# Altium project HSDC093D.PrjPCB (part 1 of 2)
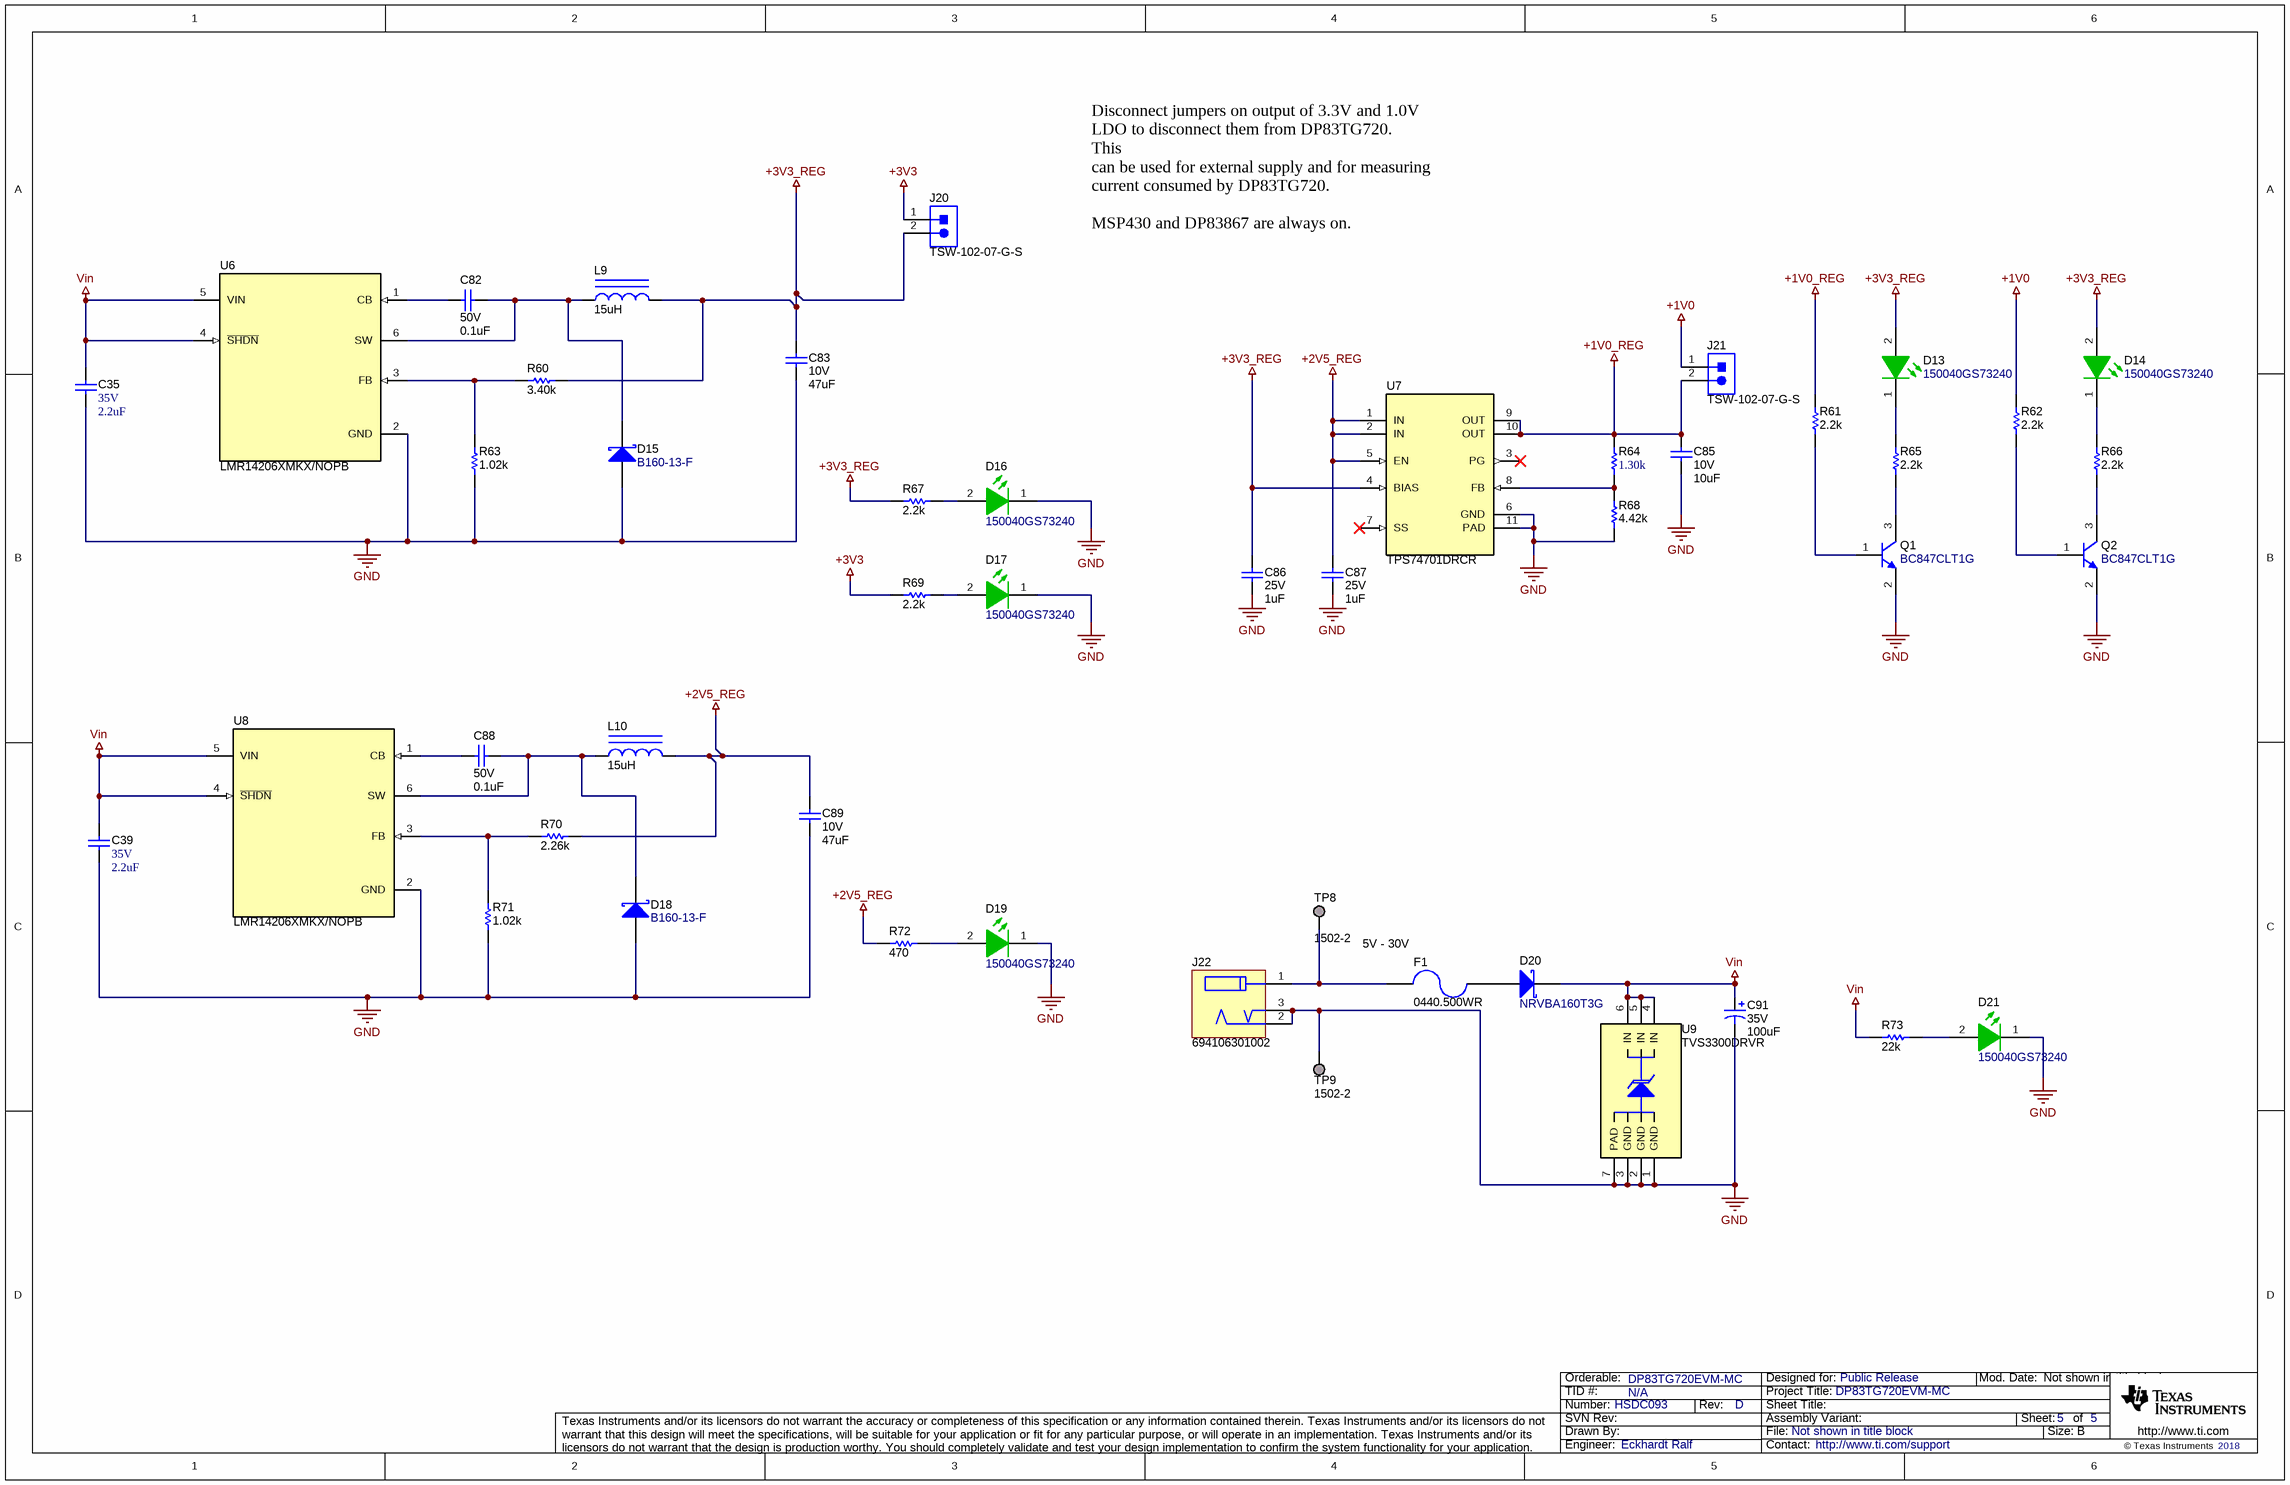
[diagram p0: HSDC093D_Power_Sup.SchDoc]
CopyrightYear: 2018; EVM_orderable: DP83TG720EVM-MC; PCB_Layout: Who did the Layout?; PCB_Rev: D; PRJ_Customer: Public Release; PRJ_Engineer: Eckhardt Ralf; PRJ_Number: HSDC093; PRJ_Title: DP83TG720EVM-MC; SCH_Rev: D; TechSupport: http://www.ti.com/support; TID: N/A
6 sheets, 280 parts. Net scope: global (net labels, ports and power ports of the same name join across sheets).
Board file: HSDC093D.PcbDoc
Sheets:
  HSDC093D_Power_Sup.SchDoc
  HSDC093D_Hardware.SchDoc
  HSDC093D_Cover_Sheet.SchDoc
  HSDC093D_Controller.SchDoc
  HSDC093D_867.SchDoc
  HSDC093D_720.SchDoc

## Sheet HSDC093D_Power_Sup.SchDoc
size 431 x 279 mm; Date: Not shown in title block; ApprovedBy: Not shown in title block; CheckedBy: Not shown in title block; Author: Not shown in title block; CompanyName: Not shown in title block; Engineer: Not shown in title block; Organization: Not shown in title block; Address1: Not shown in title block; Address2: Not shown in title block; Address3: Not shown in title block; Address4: Not shown in title block; DocumentNumber: 5; Revision: Use project parameter SCH_Rev; SheetNumber: 5; SheetTotal: 5; PageSetup: Record=PageOptions¦CenterHorizontal=True¦CenterVertical=True¦PrintScale=1.00¦XCorrection=1.00¦YCorrection=1.00¦PrintKind=0¦BorderSize=5000000¦LeftOffset=0¦BottomOffset=0¦Orientation=2¦PaperLength=1000¦PaperWidth=1000¦Scale=100¦PaperSource=15¦PrintQuality=600¦MediaType=1¦DitherType=10¦PaperKind=Letter¦PrintScaleMode=1

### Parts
C35  VDC_V: 35V  ValueDisplayed: 2.2uF  [0603]  (hidden comment: C1608X5R1V225K080AC)
C39  VDC_V: 35V  ValueDisplayed: 2.2uF  [0603]  (hidden comment: C1608X5R1V225K080AC)
C82  VDC_V: 50V  ValueDisplayed: 0.1uF  [0402]  (hidden comment: C1005X5R1H104K050BB)
C83  VDC_V: 10V  ValueDisplayed: 47uF  [0805_HV]  (hidden comment: C2012X5R1A476M125AC)
C85  VDC_V: 10V  ValueDisplayed: 10uF  [0402]  (hidden comment: GRM155R61A106ME11)
C86  VDC_V: 25V  ValueDisplayed: 1uF  [0402]  (hidden comment: GRM155R61E105KA12D)
C87  VDC_V: 25V  ValueDisplayed: 1uF  [0402]  (hidden comment: GRM155R61E105KA12D)
C88  VDC_V: 50V  ValueDisplayed: 0.1uF  [0402]  (hidden comment: C1005X5R1H104K050BB)
C89  VDC_V: 10V  ValueDisplayed: 47uF  [0805_HV]  (hidden comment: C2012X5R1A476M125AC)
C91  VDC_V: 35V  ValueDisplayed: 100uF  [CAPSMT_62_F80]  (hidden comment: EMVA350ADA101MF80G)
D13  150040GS73240  [WL-SMCC_0402_Green]
D14  150040GS73240  [WL-SMCC_0402_Green]
D15  B160-13-F  [SMA]
D16  150040GS73240  [WL-SMCC_0402_Green]
D17  150040GS73240  [WL-SMCC_0402_Green]
D18  B160-13-F  [SMA]
D19  150040GS73240  [WL-SMCC_0402_Green]
D20  NRVBA160T3G  [SMA]
D21  150040GS73240  [WL-SMCC_0402_Green]
F1  0440.500WR  [1206]
J20  TSW-102-07-G-S  [TSW-102-07-G-S]
J21  TSW-102-07-G-S  [TSW-102-07-G-S]
J22  694106301002  [Wurth_694106301002]
L9  ValueDisplayed: 15uH  [WE-TPC-LH]  (hidden comment: 744053150)
L10  ValueDisplayed: 15uH  [WE-TPC-LH]  (hidden comment: 744053150)
Q1  BC847CLT1G  [SOT-23]
Q2  BC847CLT1G  [SOT-23]
R60  ValueDisplayed: 3.40k  [0402]  (hidden comment: CRCW04023K40FKED)
R61  ValueDisplayed: 2.2k  [0402]  (hidden comment: CRCW04022K20JNED)
R62  ValueDisplayed: 2.2k  [0402]  (hidden comment: CRCW04022K20JNED)
R63  ValueDisplayed: 1.02k  [0402]  (hidden comment: CRCW04021K02FKED)
R64  ValueDisplayed: 1.30k  [0402]  (hidden comment: CRCW04021K30FKED)
R65  ValueDisplayed: 2.2k  [0402]  (hidden comment: CRCW04022K20JNED)
R66  ValueDisplayed: 2.2k  [0402]  (hidden comment: CRCW04022K20JNED)
R67  ValueDisplayed: 2.2k  [0402]  (hidden comment: CRCW04022K20JNED)
R68  ValueDisplayed: 4.42k  [0402]  (hidden comment: CRCW04024K42FKED)
R69  ValueDisplayed: 2.2k  [0402]  (hidden comment: CRCW04022K20JNED)
R70  ValueDisplayed: 2.26k  [0402]  (hidden comment: CRCW04022K26FKED)
R71  ValueDisplayed: 1.02k  [0402]  (hidden comment: CRCW04021K02FKED)
R72  ValueDisplayed: 470  [0402]  (hidden comment: RC0402FR-07470RL)
R73  ValueDisplayed: 22k  [0402]  (hidden comment: CRCW040222K0JNED)
TP8  1502-2  [Keystone1502-2]
TP9  1502-2  [Keystone1502-2]
U6  LMR14206XMKX/NOPB  [DDC0006A_N]
U7  TPS74701DRCR  [DRC0010J]
U8  LMR14206XMKX/NOPB  [DDC0006A_N]
U9  TVS3300DRVR  [DRV0006A]

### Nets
+1V0: J21.1 R62.2
+1V0_REG: C85.1 J21.2 R61.2 R64.1 U7.9(OUT) U7.10(OUT)
+2V5_REG: C87.1 C89.1 L10.2 R70.2 R72.1 U7.1(IN) U7.2(IN) U7.5(EN)
+3V3: J20.1 R69.1
+3V3_REG: C83.1 C86.1 D13.2(A) D14.2(A) J20.2 L9.2 R60.2 R67.1 U7.4(BIAS)
GND: C35.2 C39.2 C83.2 C85.2 C86.2 C87.2 C89.2 C91.2(-) D15.2(A) D16.1(K) D17.1(K) D18.2(A) D19.1(K) D21.1(K) J22.2 J22.3 Q1.2(E) Q2.2(E) R63.1 R68.1 R71.1 TP9.1 U6.2(GND) U7.6(GND) U7.11(PAD) U8.2(GND) U9.1(GND) U9.2(GND) U9.3(GND) U9.7(PAD)
Vin: C35.1 C39.1 C91.1(+) D20.1(K) R73.1 U6.4(~{SHDN}) U6.5(VIN) U8.4(~{SHDN}) U8.5(VIN) U9.4(IN) U9.5(IN) U9.6(IN)
NetC82_1: C82.1 U6.1(CB)
NetC82_2: C82.2 D15.1(K) L9.1 U6.6(SW)
NetC88_1: C88.1 U8.1(CB)
NetC88_2: C88.2 D18.1(K) L10.1 U8.6(SW)
NetD13_1: D13.1(K) R65.2
NetD14_1: D14.1(K) R66.2
NetD16_2: D16.2(A) R67.2
NetD17_2: D17.2(A) R69.2
NetD19_2: D19.2(A) R72.2
NetD20_2: D20.2(A) F1.1
NetD21_2: D21.2(A) R73.2
NetF1_2: F1.2 J22.1 TP8.1
NetQ1_1: Q1.1(B) R61.1
NetQ1_3: Q1.3(C) R65.1
NetQ2_1: Q2.1(B) R62.1
NetQ2_3: Q2.3(C) R66.1
NetR60_1: R60.1 R63.2 U6.3(FB)
NetR64_2: R64.2 R68.2 U7.8(FB)
NetR70_1: R70.1 R71.2 U8.3(FB)

Not connected (* = marked no-connect by the designer): U7 3(PG)* 7(SS)*

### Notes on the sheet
- Disconnect jumpers on output of 3.3V and 1.0V
  LDO to disconnect them from DP83TG720.
  This
  can be used for external supply and for measuring
  current consumed by DP83TG720.
  MSP430 and DP83867 are always on.
- 5V - 30V

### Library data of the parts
C35 C39 = CMP-0007020-5: CAP, CERM, 2.2 uF, 35 V, +/- 10%, X5R, 0603; Manufacturer: TDK; TaMin_C: -55°C; ESR_ohm: 7.674m; Polarized: N; SizeAreaWB_mm2: 4.68; Value1: 0.007674 ohm; U/M: EA; Value: 2.2uF; TaMax_C: 85°C; SizeZ_mm: 1; SizeX_mm: 1.6; SizeY_mm: 0.8; SizeArea_mm2: 1.28; Cap_F: 2.2µF; IRMS_A: 1.87823A; AEC Category: Q200
C82 C88 = CMP-0006279-2: CAP, CERM, 0.1 uF, 50 V, +/- 10%, X5R, 0402; Manufacturer: TDK; TaMin_C: -55°C; ESR_ohm: 0.039064; Polarized: N; SizeAreaWB_mm2: 3; Value1: 0.039064 ohm; U/M: EA; Value: 0.1uF; TaMax_C: 85°C; SizeZ_mm: 0.6; SizeX_mm: 1; SizeY_mm: 0.5; Cap_F: 100nF; IRMS_A: 814.669mA; AEC Category: Q200
C83 C89 = CMP-0007825-2: CAP, CERM, 47 uF, 10 V, +/- 20%, X5R, 0805; Manufacturer: TDK; TaMin_C: -55°C; ESR_ohm: 2.94m; Polarized: N; SizeAreaWB_mm2: 6.75; Value1: 0.00294 ohm; U/M: EA; Value: 47uF; TaMax_C: 85°C; SizeZ_mm: 1.45; SizeX_mm: 2; SizeY_mm: 1.25; Cap_Case: 0805; SizeArea_mm2: 2.5; Cap_F: 47µF; IRMS_A: 3.80451A; AEC Category: Q200
C85 = CMP-0006564-2: CAP, CERM, 10 uF, 10 V, +/- 20%, X5R, 0402; Manufacturer: MuRata; TaMin_C: -55°C; Polarized: N; SizeAreaWB_mm2: 3; Value1: Unknown; U/M: EA; Value: 10uF; TaMax_C: 85°C; SizeZ_mm: 0.6; SizeX_mm: 1; SizeY_mm: 0.5; Cap_F: 10µF; AEC Category: Q200
C86 C87 = CMP-0006608-2: CAP, CERM, 1 uF, 25 V, +/- 10%, X5R, 0402; Manufacturer: MuRata; TaMin_C: -55°C; Polarized: N; SizeAreaWB_mm2: 3; Value1: Unknown; U/M: EA; Value: 1uF; TaMax_C: 85°C; SizeZ_mm: 0.6; SizeX_mm: 1; SizeY_mm: 0.5; Cap_F: 1µF; AEC Category: Q200
C91 = CMP-0010800-1: CAP, AL, 100 uF, 35 V, +/- 20%, SMD; Manufacturer: Chemi-Con; TaMin_C: -40°C; Polarized: Y; SizeAreaWB_mm2: 73.96; Value1: Unknown; U/M: EA; Value: 100uF; TaMax_C: 85°C; SizeZ_mm: 7.7; SizeX_mm: 6.6; Cap_Case: F80; SizeArea_mm2: 43.56; CompType: Capacitor; Cap_F: 100µF; IRMS_A: 120mA; AEC Category: Q200
D13 D14 D16 D17 D19 D21 = CMP-0081765-2: LED, Green, SMD; Manufacturer: Wurth Elektronik; Vr_V: 5V; Io_A: 20mA; Tjmax_C: 95°C; Ir_A: 10µA; Power_TotalModule: 99mW; Value2: 3.2V; SizeArea_mm2: 0.5; SizeX_mm: 1; Value1: 0.099W; Angle: 120; Type: InGaN; SizeAreaWB_mm2: 3
D15 D18 = CMP-0028389-2: Diode, Schottky, 60 V, 1 A, SMA; Manufacturer: Diodes Inc.; Green_Lifecycle: Not Set; SizeAreaWB_mm2: 37.3428; Green_REACh: Incomplete; TJmax_C: 150°C; AEC Category: Q101; SizeZ_mm: 2.87; RJC_CperW: 20; Io_A: 1A; SizeArea_mm2: 16.3228; Vf_V: 700mV; Value2: 0.7V; SizeY_mm: 2.92; Vr_V: 60V; SizeX_mm: 5.59; Value: 60V
D20 = CMP-0028762-2: Diode, Schottky, 60 V, 1 A, AEC-Q101, SMA; Manufacturer: ON Semiconductor; SizeY_mm: 2.92; Value2: 0.51V; Green_Lifecycle: Active; Vf_V: 510mV; SizeAreaWB_mm2: 37.3428; SizeX_mm: 5.59; SizeZ_mm: 2.87; Green_REACh: Passed; AEC Qualified: Y; Vr_V: 60V; TJmax_C: 150°C; AEC Category: Q101; Value1: 1A; Value: 60V; SizeArea_mm2: 16.3228
F1 = CMP-0003452-2: Fuse, 0.5 A, 63VAC/VDC, SMD; Manufacturer: Littelfuse; Irating_A: 500mA; SizeAreaWB_mm2: 10.92; Interrupt_AC: 50A; VAC_V: 63V; SizeZ_mm: 1.35; SizeX_mm: 3.2; SizeY_mm: 1.6; SizeArea_mm2: 5.12; Rtyp_Ohm: 0.814; MeltingTyp: 0.02642
J20 J21 = CMP-0075405-3: Header, 100mil, 2x1, Gold, TH; Manufacturer: Samtec; Pitch_mm: 2.54; Cert_VDE: N; Gender: Male; Cert_CSA: Y; Voltage_V: 550V; Green_REACh: Passed; Current_A: 6.3A; Green_Lifecycle: Active; Row_Count: 1
J22 = CMP-0054778-4: WR-DC DC Power Jack, R/A, TH; Manufacturer: Wurth Elektronik; Gender: Male
L9 L10 = CMP-0064420-2: Inductor, Shielded Drum Core, Ferrite, 15 uH, 1.15 A, 0.07 ohm, SMD; Manufacturer: Wurth Elektronik; Isat: 1.15A @ 35% inductance drop; Irms: 1.38A @ 30C rise; Green_Lifecycle: Active; SizeAreaWB_mm2: 60.84; DCR_ohm: 0.07; Green_REACh: Passed; Value: 15uH; Imax_A: 1.15A; SizeZ_mm: 2.8; SizeX_mm: 5.8; SizeArea_mm2: 33.64; Ind_H: 15µH; AEC Category: Q200
Q1 Q2 = CMP-0000376-2: Transistor, NPN, 45 V, 0.1 A, SOT-23; Manufacturer: ON Semiconductor; TaMax_C: 150°C; Value2: 800; Value1: 0.1 A; Vcesat1_V: 700mV; SizeX_mm: 2.5; SizeY_mm: 3; TaMin_C: -55°C; IcRated_A: 100mA; CompType: BJT; SizeZ_mm: 1.1; Value: 45 V; SizeArea_mm2: 7.5; NPN: 1; Vceo_V: 45V; PNP: 0; AEC Category: Q101; SizeAreaWB_mm2: 14; U/M: EA
R60 = CMP-0026334-2: RES, 3.40 k, 1%, 0.063 W, AEC-Q200 Grade 0, 0402; Manufacturer: Vishay-Dale; Power_W: 63mW; TempCo: 100 ppm/C; Value_Code: 3k40; Value: 3.40k; EIA_Code: E96; Res_ohm: 3.4k; SizeX_mm: 1; SizeY_mm: 0.5; SizeZ_mm: 0.6; Value2: 0.063W; AEC Qualified: Y; VDC_V: 50V; AEC Category: Q200; AEC Grade: 0
R61 R62 R65-R67 R69 = CMP-0026890-5: RES, 2.2 k, 5%, 0.063 W, AEC-Q200 Grade 0, 0402; Manufacturer: Vishay-Dale; Power_W: 63mW; TempCo: 200 ppm/C; Value_Code: 2k20; Value: 2.2k; EIA_Code: E24; SizeX_mm: 1; SizeY_mm: 0.5; SizeZ_mm: 0.6; Value2: 0.063W; AEC Qualified: Y; VDC_V: 50V; AEC Category: Q200; AEC Grade: 0
R63 R71 = CMP-0026072-3: RES, 1.02 k, 1%, 0.063 W, AEC-Q200 Grade 0, 0402; Manufacturer: Vishay-Dale; Power_W: 63mW; TempCo: 100 ppm/C; Value_Code: 1k02; Value: 1.02k; EIA_Code: E96; SizeX_mm: 1; SizeY_mm: 0.5; SizeZ_mm: 0.6; Value2: 0.063W; AEC Qualified: Y; VDC_V: 50V; AEC Category: Q200; AEC Grade: 0
R64 = CMP-0026082-3: RES, 1.30 k, 1%, 0.063 W, AEC-Q200 Grade 0, 0402; Manufacturer: Vishay-Dale; Power_W: 63mW; TempCo: 100 ppm/C; Value_Code: 1k30; Value: 1.30k; EIA_Code: E96; Res_ohm: 1.3k; SizeX_mm: 1; SizeY_mm: 0.5; SizeZ_mm: 0.6; Value2: 0.063W; AEC Qualified: Y; VDC_V: 50V; AEC Category: Q200; AEC Grade: 0
R68 = CMP-0026409-2: RES, 4.42 k, 1%, 0.063 W, AEC-Q200 Grade 0, 0402; Manufacturer: Vishay-Dale; Power_W: 63mW; TempCo: 100 ppm/C; Value_Code: 4k42; Value: 4.42k; EIA_Code: E96; SizeX_mm: 1; SizeY_mm: 0.5; SizeZ_mm: 0.6; Value2: 0.063W; AEC Qualified: Y; VDC_V: 50V; AEC Category: Q200; AEC Grade: 0
R70 = CMP-0026233-2: RES, 2.26 k, 1%, 0.063 W, AEC-Q200 Grade 0, 0402; Manufacturer: Vishay-Dale; Power_W: 63mW; TempCo: 100 ppm/C; Value_Code: 2k26; Value: 2.26k; EIA_Code: E96; SizeX_mm: 1; SizeY_mm: 0.5; SizeZ_mm: 0.6; Value2: 0.063W; AEC Qualified: Y; VDC_V: 50V; AEC Category: Q200; AEC Grade: 0
R72 = CMP-0026736-1: RES, 470, 1%, 0.063 W, 0402; Manufacturer: Yageo America; Power_W: 63mW; TempCo: 100 ppm/C; Value_Code: 470R; U/M: EA; Value: 470; SizeX_mm: 1; SizeY_mm: 0.5; SizeZ_mm: 0.6; Value2: 0.063W; AEC Qualified: N; VDC_V: 50V; AEC Category: Q200
R73 = CMP-0026879-3: RES, 22 k, 5%, 0.063 W, AEC-Q200 Grade 0, 0402; Manufacturer: Vishay-Dale; Power_W: 63mW; TempCo: 200 ppm/C; Value_Code: 22k0; Value: 22k; EIA_Code: E24; SizeX_mm: 1; SizeY_mm: 0.5; SizeZ_mm: 0.6; Value2: 0.063W; AEC Qualified: Y; VDC_V: 50V; AEC Category: Q200; AEC Grade: 0
TP8 TP9 = CMP-0055113-1: Terminal, Turret, TH, Double; Manufacturer: Keystone; CT: FALSE; Green_REACh: Passed; CompType: Turret Terminal; Green_Lifecycle: Active
U6 U8 = CMP-0076377-2: SIMPLE SWITCHER(R) 4.5V to 42V, 0.6A Step-Down DC/DC Switching Regulator in SOT-23 Package, DDC0006A (SOT-23-T-6); Alternate PartNumber: LMR14206XMKE/NOPB; Manufacturer: Texas Instruments; SizeZ_mm: 0.87; SizeX_mm: 1.65; SizeY_mm: 2.95; SizeArea_mm2: 4.8675; CompType: IC; U/M: EA; SizeAreaWB_mm2: 10.4675
U7 = CMP-0036362-5: Single Output LDO, 500mA, Adj. (0.8 to 3.6V), Programmable Soft-Start, DRC0010J (VSON-10); Manufacturer: Texas Instruments; Vout Adj(Min)(V): 0.8; Rating: Catalog; Iq(Typ)(mA): 1; CompType: IC; Accuracy(%): 2; SizeX_mm: 3; Vdo(Typ)(mV): 50; Vin(Max)(V): 5.5; AEC Category: Q200; Vout Adj(Max)(V): 3.6; Power Good: TRUE; AEC Qualified: N; SizeAreaWB_mm2: 16; SizeArea_mm2: 9; Iout(Max)(A): 0.5
U9 = CMP-0013424-7: 33-V Precision Surge Protection Clamp, DRV0006A (WSON-6); Manufacturer: Texas Instruments; Alternate PartNumber: TVS3300DRVT; SizeX_mm: 2; CompType: IC; SizeZ_mm: 0.8; SizeArea_mm2: 4; SizeAreaWB_mm2: 9; U/M: EA

## Sheet HSDC093D_Hardware.SchDoc
size 431 x 279 mm; Date: Not shown in title block; ApprovedBy: Not shown in title block; CheckedBy: Not shown in title block; Author: Not shown in title block; CompanyName: Not shown in title block; Engineer: Not shown in title block; Organization: Not shown in title block; Address1: Not shown in title block; Address2: Not shown in title block; Address3: Not shown in title block; Address4: Not shown in title block; DocumentNumber: 1; Revision: Use project parameter SCH_Rev; SheetNumber: 1; SheetTotal: 5; PageSetup: Record=PageOptions¦CenterHorizontal=True¦CenterVertical=True¦PrintScale=1.00¦XCorrection=1.00¦YCorrection=1.00¦PrintKind=0¦BorderSize=5000000¦LeftOffset=0¦BottomOffset=0¦Orientation=2¦PaperLength=1000¦PaperWidth=1000¦Scale=100¦PaperSource=15¦PrintQuality=600¦MediaType=1¦DitherType=10¦PaperKind=Letter¦PrintScaleMode=1
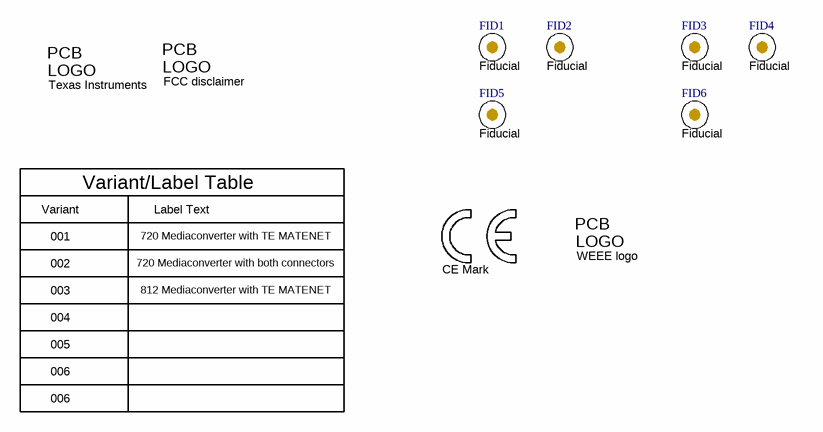
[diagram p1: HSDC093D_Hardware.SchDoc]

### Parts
FID1  Fiducial  [Fiducial10-30]
FID2  Fiducial  [Fiducial10-30]
FID3  Fiducial  [Fiducial10-30]
FID4  Fiducial  [Fiducial10-30]
FID5  Fiducial  [Fiducial10-30]
FID6  Fiducial  [Fiducial10-30]
Logo1  CE Mark  [CE_Mark_5mm]  (no BOM)
Logo2  FCC disclaimer  [FCC_disclaimer]  (no BOM)
Logo3  Texas Instruments  [TI_Stacked_Overlay_Small]  (no BOM)
Logo4  WEEE logo  [WEEE_Minimum]  (no BOM)

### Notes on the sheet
- Variant/Label Table
- Variant
- 001
- Label Text
- 720 Mediaconverter with TE MATENET
- 002
- 003
- 004
- 720 Mediaconverter with both connectors
- 812 Mediaconverter with TE MATENET
- 005
- 006

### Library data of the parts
FID1-FID6 = CMP-0077181-1: Fiducial mark.  There is nothing to buy or mount.
Logo1 = CMP-0074844-1: SymbolCreator: a0412235
Logo2 = CMP-0074847-1: FCC_disclaimer; Library Reference: Logo
Logo3 = CMP-0074838-1: Texas Instrument Corporate Signature; Library Reference: Logo; SymbolCreator: a0412235; Lib Reference: TI_Logo
Logo4 = CMP-0074769-1

## Sheet HSDC093D_Cover_Sheet.SchDoc
size 431 x 279 mm; Date: Not shown in title block; ApprovedBy: Not shown in title block; CheckedBy: Not shown in title block; Author: Not shown in title block; CompanyName: Not shown in title block; Engineer: Not shown in title block; Organization: Not shown in title block; Address1: Not shown in title block; Address2: Not shown in title block; Address3: Not shown in title block; Address4: Not shown in title block; DocumentNumber: 1; Revision: Use project parameter SCH_Rev; SheetNumber: 1; SheetTotal: 5; PageSetup: Record=PageOptions¦CenterHorizontal=True¦CenterVertical=True¦PrintScale=1.00¦XCorrection=1.00¦YCorrection=1.00¦PrintKind=0¦BorderSize=5000000¦LeftOffset=0¦BottomOffset=0¦Orientation=2¦PaperLength=1000¦PaperWidth=1000¦Scale=100¦PaperSource=15¦PrintQuality=600¦MediaType=1¦DitherType=10¦PaperKind=Letter¦PrintScaleMode=1

## Sheet HSDC093D_Controller.SchDoc
size 431 x 279 mm; Date: Not shown in title block; ApprovedBy: Not shown in title block; CheckedBy: Not shown in title block; Author: Not shown in title block; CompanyName: Not shown in title block; Engineer: Not shown in title block; Organization: Not shown in title block; Address1: Not shown in title block; Address2: Not shown in title block; Address3: Not shown in title block; Address4: Not shown in title block; DocumentNumber: 4; Revision: Use project parameter SCH_Rev; SheetNumber: 4; SheetTotal: 5; PageSetup: Record=PageOptions¦CenterHorizontal=True¦CenterVertical=True¦PrintScale=1.00¦XCorrection=1.00¦YCorrection=1.00¦PrintKind=0¦BorderSize=5000000¦LeftOffset=0¦BottomOffset=0¦Orientation=2¦PaperLength=1000¦PaperWidth=1000¦Scale=100¦PaperSource=15¦PrintQuality=600¦MediaType=1¦DitherType=10¦PaperKind=Letter¦PrintScaleMode=1
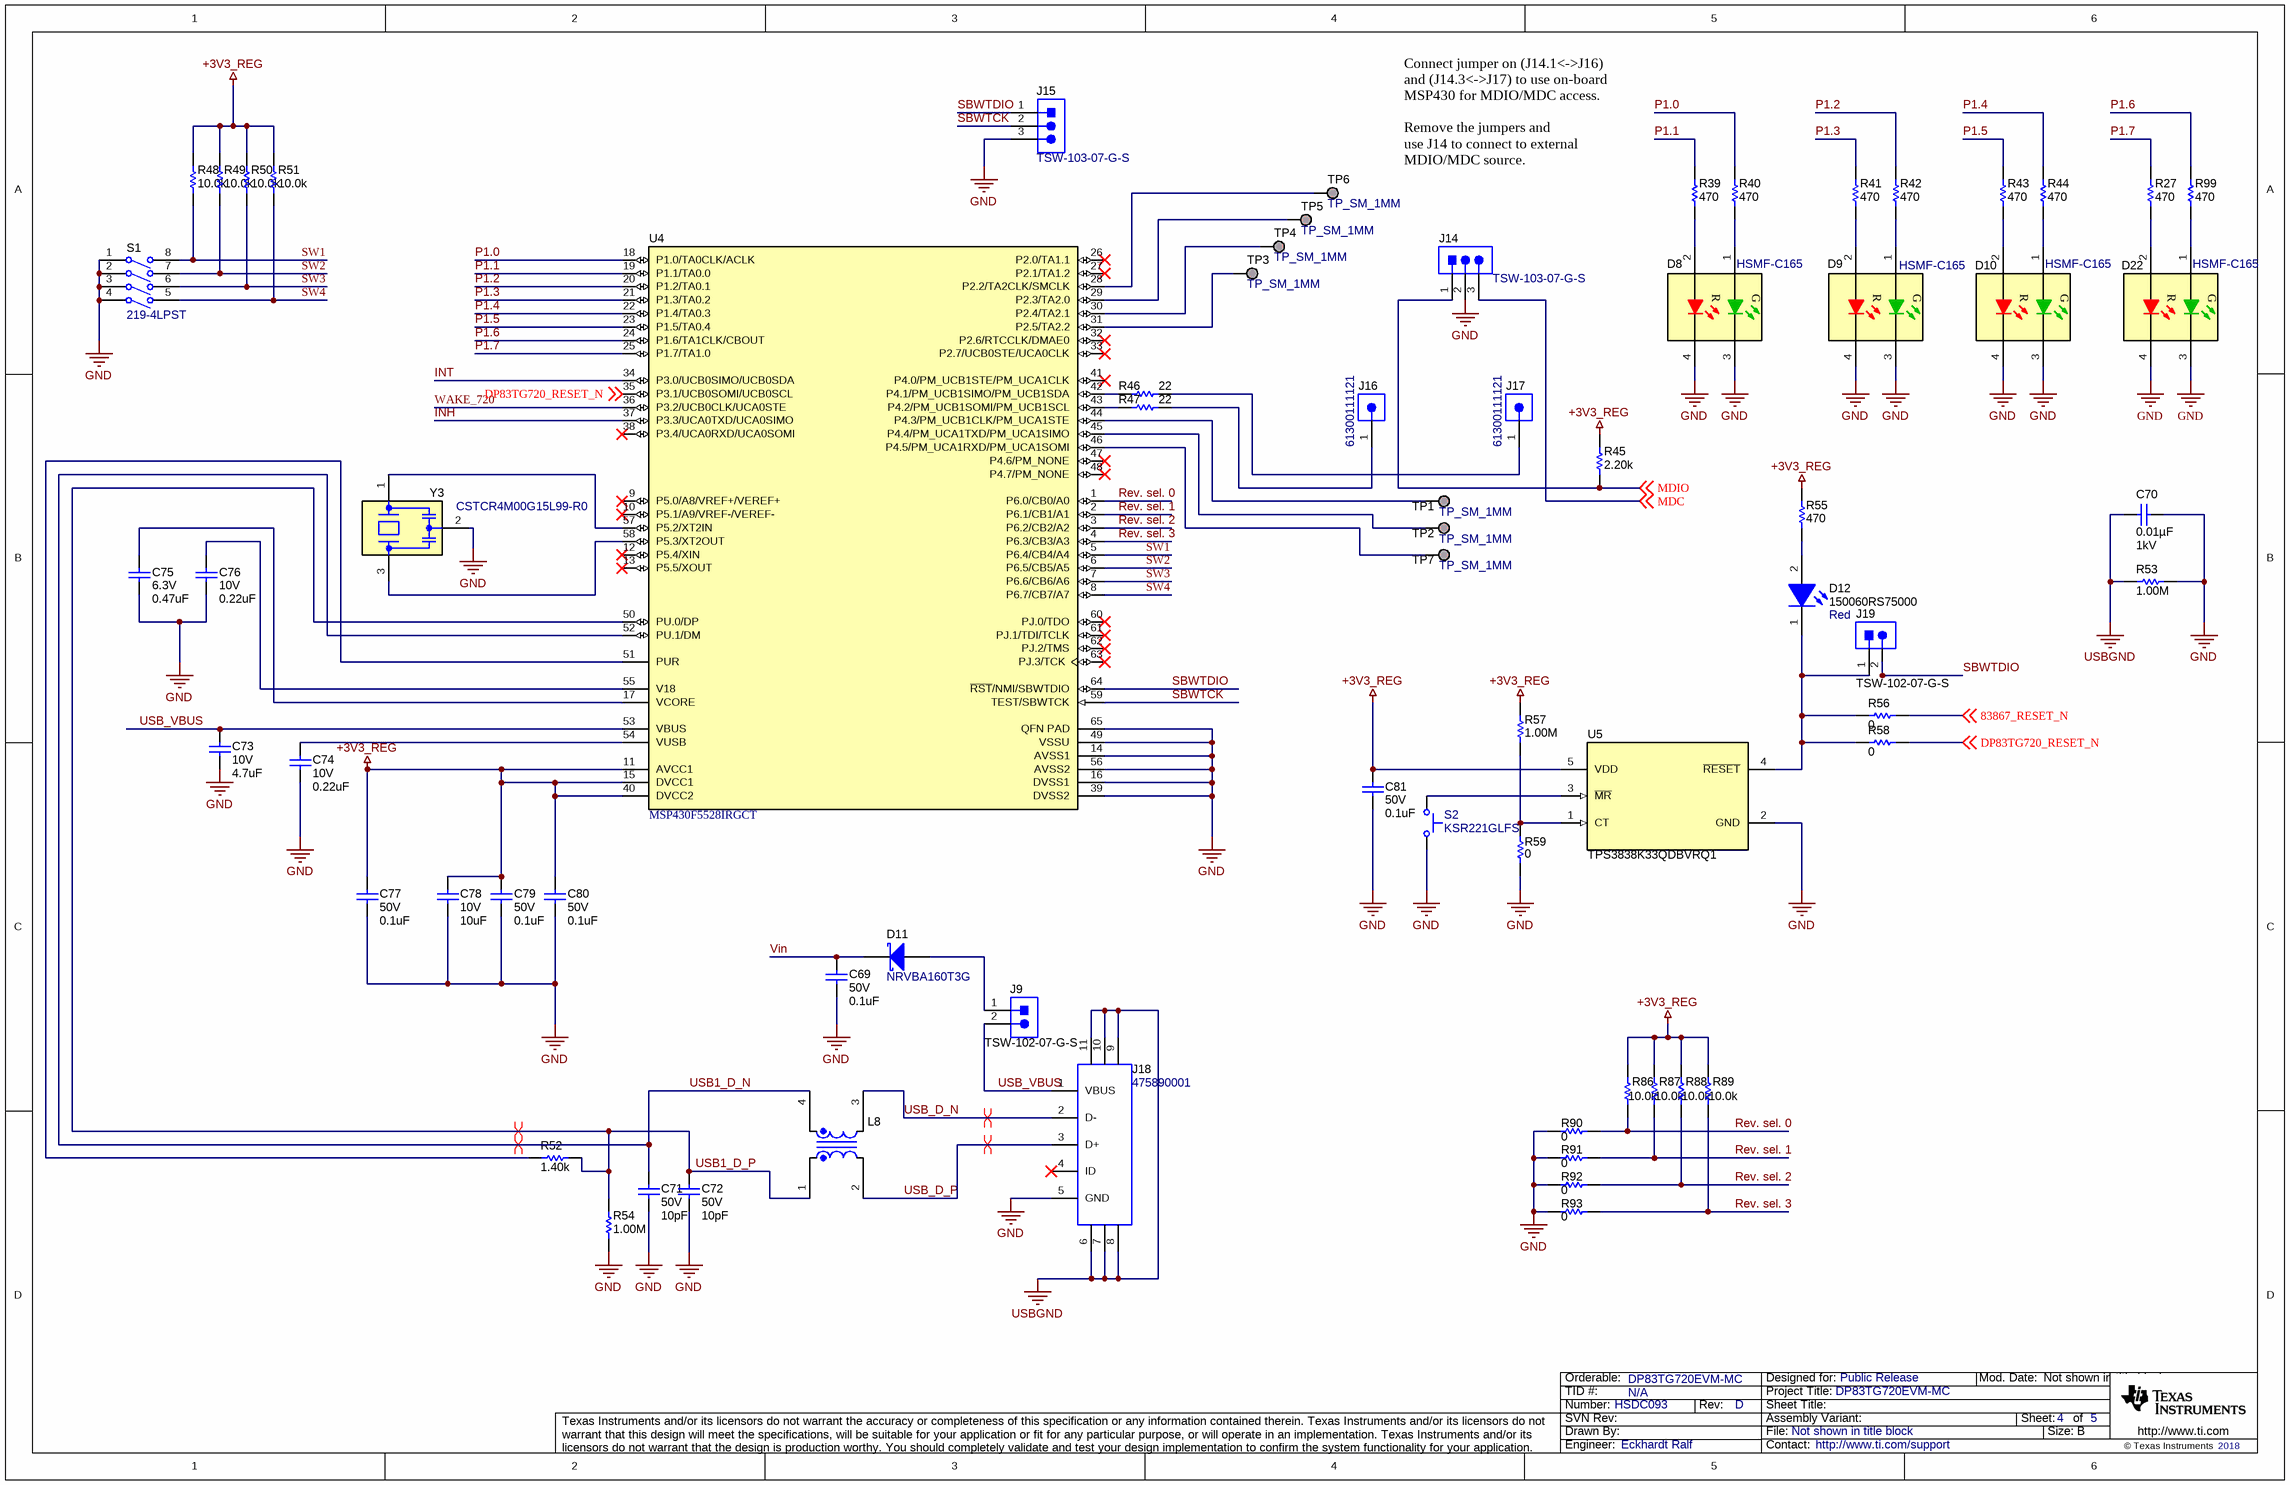
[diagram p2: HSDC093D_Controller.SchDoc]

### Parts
C69  VDC_V: 50V  ValueDisplayed: 0.1uF  [0402]  (hidden comment: C1005X5R1H104K050BB)
C70  ValueDisplayed: 0.01µF  VDC_V: 1kV  [1206]  (hidden comment: C1206X103KDRAC7800)
C71  VDC_V: 50V  ValueDisplayed: 10pF  [0402]  (hidden comment: GRM1555C1H100FA01D)
C72  VDC_V: 50V  ValueDisplayed: 10pF  [0402]  (hidden comment: GRM1555C1H100FA01D)
C73  VDC_V: 10V  ValueDisplayed: 4.7uF  [0402_065]  (hidden comment: C1005X5R1A475K050BC)
C74  VDC_V: 10V  ValueDisplayed: 0.22uF  [0402]  (hidden comment: GRM155R61A224KE19D)
C75  VDC_V: 6.3V  ValueDisplayed: 0.47uF  [0402]  (hidden comment: 04026D474KAT2A)
C76  VDC_V: 10V  ValueDisplayed: 0.22uF  [0402]  (hidden comment: GRM155R61A224KE19D)
C77  VDC_V: 50V  ValueDisplayed: 0.1uF  [0402]  (hidden comment: C1005X5R1H104K050BB)
C78  VDC_V: 10V  ValueDisplayed: 10uF  [0402]  (hidden comment: GRM155R61A106ME11)
C79  VDC_V: 50V  ValueDisplayed: 0.1uF  [0402]  (hidden comment: C1005X5R1H104K050BB)
C80  VDC_V: 50V  ValueDisplayed: 0.1uF  [0402]  (hidden comment: C1005X5R1H104K050BB)
C81  VDC_V: 50V  ValueDisplayed: 0.1uF  [0402]  (hidden comment: C1005X5R1H104K050BB)
D8  HSMF-C165  [HSMF-C165_RG]
D9  HSMF-C165  [HSMF-C165_RG]
D10  HSMF-C165  [HSMF-C165_RG]
D11  NRVBA160T3G  [SMA]
D12  150060RS75000  value Red  [WL-SMCW_RED]
D22  HSMF-C165  [HSMF-C165_RG]
J9  TSW-102-07-G-S  [TSW-102-07-G-S]
J14  TSW-103-07-G-S  [TSW-103-07-G-S]
J15  TSW-103-07-G-S  [TSW-103-07-G-S]
J16  61300111121  [WURTH_61300111121]
J17  61300111121  [WURTH_61300111121]
J18  475890001  [Molex_0475890001]
J19  TSW-102-07-G-S  [TSW-102-07-G-S]
L8  744232090  [WE-CNSW_1206]  (value not drawn)
R27  ValueDisplayed: 470  [0402]  (hidden comment: RC0402FR-07470RL)
R39  ValueDisplayed: 470  [0402]  (hidden comment: RC0402FR-07470RL)
R40  ValueDisplayed: 470  [0402]  (hidden comment: RC0402FR-07470RL)
R41  ValueDisplayed: 470  [0402]  (hidden comment: RC0402FR-07470RL)
R42  ValueDisplayed: 470  [0402]  (hidden comment: RC0402FR-07470RL)
R43  ValueDisplayed: 470  [0402]  (hidden comment: RC0402FR-07470RL)
R44  ValueDisplayed: 470  [0402]  (hidden comment: RC0402FR-07470RL)
R45  ValueDisplayed: 2.20k  [0402]  (hidden comment: ERJ-2RKF2201X)
R46  ValueDisplayed: 22  [0402]  (hidden comment: ERJ-2GEJ220X)
R47  ValueDisplayed: 22  [0402]  (hidden comment: ERJ-2GEJ220X)
R48  ValueDisplayed: 10.0k  [0402]  (hidden comment: RT0402BRD0710KL)
R49  ValueDisplayed: 10.0k  [0402]  (hidden comment: RT0402BRD0710KL)
R50  ValueDisplayed: 10.0k  [0402]  (hidden comment: RT0402BRD0710KL)
R51  ValueDisplayed: 10.0k  [0402]  (hidden comment: RT0402BRD0710KL)
R52  ValueDisplayed: 1.40k  [0402]  (hidden comment: CRCW04021K40FKED)
R53  ValueDisplayed: 1.00M  [0603]  (hidden comment: RMCF0603FG1M00)
R54  ValueDisplayed: 1.00M  [0402]  (hidden comment: ERJ-2RKF1004X)
R55  ValueDisplayed: 470  [0402]  (hidden comment: RC0402FR-07470RL)
R56  ValueDisplayed: 0  [0402]  (hidden comment: CRCW04020000Z0EDHP)
R57  ValueDisplayed: 1.00M  [0402]  (hidden comment: ERJ-2RKF1004X)
R58  ValueDisplayed: 0  [0402]  (hidden comment: CRCW04020000Z0EDHP)
R59  ValueDisplayed: 0  [0402]  (hidden comment: CRCW04020000Z0EDHP)
R86  ValueDisplayed: 10.0k  [0402]  (hidden comment: RT0402BRD0710KL)
R87  ValueDisplayed: 10.0k  [0402]  (hidden comment: RT0402BRD0710KL)
R88  ValueDisplayed: 10.0k  [0402]  (hidden comment: RT0402BRD0710KL)
R89  ValueDisplayed: 10.0k  [0402]  (hidden comment: RT0402BRD0710KL)
R90  ValueDisplayed: 0  [0402]  (hidden comment: CRCW04020000Z0EDHP)
R91  ValueDisplayed: 0  [0402]  (hidden comment: CRCW04020000Z0EDHP)
R92  ValueDisplayed: 0  [0402]  (hidden comment: CRCW04020000Z0EDHP)
R93  ValueDisplayed: 0  [0402]  (hidden comment: CRCW04020000Z0EDHP)
R99  ValueDisplayed: 470  [0402]  (hidden comment: RC0402FR-07470RL)
S1  219-4LPST  [SW_219-4LPST]
S2  KSR221GLFS  [KSR]
TP1  TP_SM_1MM  [TP_SM_1MM]  (no BOM)
TP2  TP_SM_1MM  [TP_SM_1MM]  (no BOM)
TP3  TP_SM_1MM  [TP_SM_1MM]  (no BOM)
TP4  TP_SM_1MM  [TP_SM_1MM]  (no BOM)
TP5  TP_SM_1MM  [TP_SM_1MM]  (no BOM)
TP6  TP_SM_1MM  [TP_SM_1MM]  (no BOM)
TP7  TP_SM_1MM  [TP_SM_1MM]  (no BOM)
U4  MSP430F5528IRGCT  [RGC0064B]
U5  TPS3838K33QDBVRQ1  [DBV0005A_N]
Y3  CSTCR4M00G15L99-R0  [Murata_CSTCR_G15L]

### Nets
+3V3_REG: C77.1 C78.1 C79.1 C80.1 C81.1 R45.2 R48.2 R49.2 R50.2 R51.2 R55.2 R57.1 R86.2 R87.2 R88.2 R89.2 U4.11(AVCC1) U4.15(DVCC1) U4.40(DVCC2) U5.5(VDD)
GND: C69.2 C70.1 C71.1 C72.1 C73.2 C74.1 C75.1 C76.2 C77.2 C78.2 C79.2 C80.2 C81.2 D8.3(K) D8.4(K) D9.3(K) D9.4(K) D10.3(K) D10.4(K) D22.3(K) D22.4(K) J14.2 J15.3 J18.5(GND) R53.2 R54.2 R59.1 R90.2 R91.2 R92.2 R93.2 S1.1(A1) S1.2(A2) S1.3(A3) S1.4(A4) S2.2 U4.14(AVSS1) U4.16(DVSS1) U4.39(DVSS2) U4.49(VSSU) U4.56(AVSS2) U4.65(QFN_PAD) U5.2(GND) Y3.2(GND)
USBGND: C70.2 J18.6 J18.7 J18.8 J18.9 J18.10 J18.11 R53.1
Vin: C69.1 D11.1(K)
83867_RESET_N: R56.2 ; off-sheet 83867_RESET_N
DP83TG720_RESET_N: R58.2 U4.35(P3.1/UCB0SOMI/UCB0SCL) ; off-sheet DP83TG720_RESET_N
INH: U4.37(P3.3/UCA0TXD/UCA0SIMO)
INT: U4.34(P3.0/UCB0SIMO/UCB0SDA)
MDC: J14.3 ; off-sheet MDC
MDIO: J14.1 R45.1 ; off-sheet MDIO
P1.0: R40.2 U4.18(P1.0/TA0CLK/ACLK)
P1.1: R39.2 U4.19(P1.1/TA0.0)
P1.2: R42.2 U4.20(P1.2/TA0.1)
P1.3: R41.2 U4.21(P1.3/TA0.2)
P1.4: R44.2 U4.22(P1.4/TA0.3)
P1.5: R43.2 U4.23(P1.5/TA0.4)
P1.6: R99.2 U4.24(P1.6/TA1CLK/CBOUT)
P1.7: R27.2 U4.25(P1.7/TA1.0)
Rev. sel. 0: R86.1 R90.1 U4.1(P6.0/CB0/A0)
Rev. sel. 1: R87.1 R91.1 U4.2(P6.1/CB1/A1)
Rev. sel. 2: R88.1 R92.1 U4.3(P6.2/CB2/A2)
Rev. sel. 3: R89.1 R93.1 U4.4(P6.3/CB3/A3)
SBWTCK: J15.2 U4.59(TEST/SBWTCK)
SBWTDIO: J15.1 J19.2 U4.64(~{RST}/NMI/SBWTDIO)
SW1: R48.1 S1.8(B1) U4.5(P6.4/CB4/A4)
SW2: R49.1 S1.7(B2) U4.6(P6.5/CB5/A5)
SW3: R50.1 S1.6(B3) U4.7(P6.6/CB6/A6)
SW4: R51.1 S1.5(B4) U4.8(P6.7/CB7/A7)
USB1_D_N: C71.2 L8.4 U4.52(PU.1/DM)
USB1_D_P: C72.2 L8.1 R52.2 R54.1 U4.50(PU.0/DP)
USB_D_N: J18.2(D-) L8.3
USB_D_P: J18.3(D+) L8.2
USB_VBUS: C73.1 J9.2 J18.1(VBUS) U4.53(VBUS)
WAKE_720: U4.36(P3.2/UCB0CLK/UCA0STE)
NetC74_2: C74.2 U4.54(VUSB)
NetC75_2: C75.2 U4.17(VCORE)
NetC76_1: C76.1 U4.55(V18)
NetD8_1: D8.1(A) R40.1
NetD8_2: D8.2(A) R39.1
NetD9_1: D9.1(A) R42.1
NetD9_2: D9.2(A) R41.1
NetD10_1: D10.1(A) R44.1
NetD10_2: D10.2(A) R43.1
NetD11_2: D11.2(A) J9.1
NetD12_1: D12.1(K) J19.1 R56.1 R58.1 U5.4(~{RESET})
NetD12_2: D12.2(A) R55.1
NetD22_1: D22.1(A) R99.1
NetD22_2: D22.2(A) R27.1
NetJ16_1: J16.1 R47.2
NetJ17_1: J17.1 R46.2
NetR46_1: R46.1 U4.42(P4.1/PM_UCB1SIMO/PM_UCB1SDA)
NetR47_1: R47.1 U4.43(P4.2/PM_UCB1SOMI/PM_UCB1SCL)
NetR52_1: R52.1 U4.51(PUR)
NetR57_2: R57.2 R59.2 U5.1(CT)
NetS2_1: S2.1 U5.3(~{MR})
NetTP1_1: TP1.1 U4.44(P4.3/PM_UCB1CLK/PM_UCA1STE)
NetTP2_1: TP2.1 U4.45(P4.4/PM_UCA1TXD/PM_UCA1SIMO)
NetTP3_1: TP3.1 U4.31(P2.5/TA2.2)
NetTP4_1: TP4.1 U4.30(P2.4/TA2.1)
NetTP5_1: TP5.1 U4.29(P2.3/TA2.0)
NetTP6_1: TP6.1 U4.28(P2.2/TA2CLK/SMCLK)
NetTP7_1: TP7.1 U4.46(P4.5/PM_UCA1RXD/PM_UCA1SOMI)
NetU4_57: U4.57(P5.2/XT2IN) Y3.1(In)
NetU4_58: U4.58(P5.3/XT2OUT) Y3.3(Out)

Not connected (* = marked no-connect by the designer): J18 4(ID)*; U4 9(P5.0/A8/VREF+/VEREF+)* 10(P5.1/A9/VREF-/VEREF-)* 12(P5.4/XIN)* 13(P5.5/XOUT)* 26(P2.0/TA1.1)* 27(P2.1/TA1.2)* 32(P2.6/RTCCLK/DMAE0)* 33(P2.7/UCB0STE/UCA0CLK)* 38(P3.4/UCA0RXD/UCA0SOMI)* 41(P4.0/PM_UCB1STE/PM_UCA1CLK)* 47(P4.6/PM_NONE)* 48(P4.7/PM_NONE)* 60(PJ.0/TDO)* 61(PJ.1/TDI/TCLK)* 62(PJ.2/TMS)* 63(PJ.3/TCK)*

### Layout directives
differential pair: USB1_D_N, USB1_D_P, USB_D_N, USB_D_P

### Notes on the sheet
- Connect jumper on (J14.1<->J16)
  and (J14.3<->J17) to use on-board MSP430 for MDIO/MDC access.
  Remove the jumpers and
  use J14 to connect to external
  MDIO/MDC source.

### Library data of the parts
C69 C77 C79-C81 = CMP-0006279-2: as C82 on sheet HSDC093D_Power_Sup
C70 = CMP-0085177-1: CAP, CERM, 0.01 µF, 1000 V,+/- 10%, X7R, 1206; Manufacturer: Kemet; SizeZ_mm: 1.35; SizeArea_mm2: 5.12; AEC Category: Q200; Cap_F: 10nF; U/M: EA; SizeY_mm: 1.6; SizeX_mm: 3.2; Value2: 1000V; TaMax_C: 125°C; Polarized: N; SizeAreaWB_mm2: 10.92; Value: 0.01uF; TaMin_C: -55°C
C71 C72 = CMP-0064916-2: CAP, CERM, 10 pF, 50 V,+/- 1%, C0G/NP0, 0402; Manufacturer: MuRata; TaMin_C: -55°C; Polarized: N; SizeAreaWB_mm2: 3; Value1: Unknown; U/M: EA; Value: 10pF; TaMax_C: 125°C; SizeZ_mm: 0.6; SizeX_mm: 1; SizeY_mm: 0.5; AEC Category: Q200
C73 = CMP-0006268-2: CAP, CERM, 4.7 uF, 10 V, +/- 10%, X5R, 0402; Manufacturer: TDK; TaMin_C: -55°C; ESR_ohm: 3.417m; Polarized: N; SizeAreaWB_mm2: 3; Value1: 0.003417 ohm; U/M: EA; Value: 4.7uF; TaMax_C: 85°C; SizeZ_mm: 0.65; SizeX_mm: 1; SizeY_mm: 0.5; Cap_F: 4.7µF; IRMS_A: 2.7063A; AEC Category: Q200
C74 C76 = CMP-0006570-2: CAP, CERM, 0.22 uF, 10 V, +/- 10%, X5R, 0402; Manufacturer: MuRata; TaMin_C: -55°C; Polarized: N; SizeAreaWB_mm2: 3; Value1: Unknown; U/M: EA; Value: 0.22uF; TaMax_C: 85°C; SizeZ_mm: 0.6; SizeX_mm: 1; SizeY_mm: 0.5; Cap_F: 220nF; AEC Category: Q200
C75 = CMP-0006199-2: CAP, CERM, 0.47 uF, 6.3 V, +/- 10%, X5R, 0402; Manufacturer: AVX; TaMin_C: -55°C; Polarized: N; SizeAreaWB_mm2: 3; Value1: Unknown; U/M: EA; Value: 0.47uF; TaMax_C: 85°C; SizeZ_mm: 0.6; SizeX_mm: 1; SizeY_mm: 0.5; Cap_F: 470nF; AEC Category: Q200
C78 = CMP-0006564-2: as C85 on sheet HSDC093D_Power_Sup
D8-D10 D22 = CMP-0002934-2: LED, Rg, SMD; Manufacturer: Avago; Io_A: 20mA; Vr_V: 5V; Tjmax_C: 85°C; Value1: W; U/M: EA; Angle: 120; Ir_A: 100µA; Vf_V: 2.2V; LuminousIntensity_IV: 20
D11 = CMP-0028762-2: as D20 on sheet HSDC093D_Power_Sup
D12 = CMP-0002947-3: LED, Red, SMD; Manufacturer: Wurth Elektronik; Value1: 0.072W; Vf_V: 2V; Angle: 140; Tjmax_C: 85°C; Type: AlInGaP; Vr_V: 5V; Io_A: 30mA; Power_TotalModule: 72mW
J9 J19 = CMP-0075405-3: as J20 on sheet HSDC093D_Power_Sup
J14 J15 = CMP-0075407-2: Header, 100mil, 3x1, Gold, TH; Manufacturer: Samtec; Pitch_mm: 2.54; Cert_VDE: N; Gender: Male; Cert_CSA: Y; Voltage_V: 550V; Green_REACh: Passed; Current_A: 6.3A; Green_Lifecycle: Active; Row_Count: 1
J16 J17 = CMP-0054792-1: Header, 2.54 mm, 1x1, Gold, TH; Manufacturer: Wurth Elektronik; CNHeader: TRUE; CT: FALSE
J18 = CMP-0055301-1: Connector, Receptacle, Micro-USB Type AB, R/A, Bottom Mount SMT; Manufacturer: Molex; CNHeader: FALSE; Green_Lifecycle: Active; Gender: Female; Green_REACh: Passed; CompType: USB; CT: TRUE
L8 = CMP-0013079-2: Coupled inductor,  A, 0.3 ohm, SMD; Manufacturer: Wurth Elektronik; DCR_ohm: 0.3
R27 R39-R44 R55 R99 = CMP-0026736-1: as R72 on sheet HSDC093D_Power_Sup
R45 = CMP-0026681-1: RES, 2.20 k, 1%, 0.1 W, 0402; Manufacturer: Panasonic; Power_W: 100mW; TempCo: 100 ppm/C; Value_Code: 2k20; U/M: EA; Value: 2.20k; Res_ohm: 2.2k; SizeX_mm: 1; SizeY_mm: 0.5; SizeZ_mm: 0.6; Value2: 0.1W; VDC_V: 50V; AEC Category: Q200
R46 R47 = CMP-0026997-2: RES, 22, 5%, 0.1 W, AEC-Q200 Grade 0, 0402; Manufacturer: Panasonic; Power_W: 100mW; TempCo: 200 ppm/C; Value_Code: 22R0; U/M: EA; Value: 22; EIA_Code: E24; SizeX_mm: 1; SizeY_mm: 0.5; SizeZ_mm: 0.6; Value2: 0.1W; AEC Qualified: Y; AEC Grade: 0; AEC Category: Q200
R48-R51 R86-R89 = CMP-0065360-1: RES, 10.0 k, .1%, .0625 W, 0402; Manufacturer: Yageo America; Power_W: 62.5mW; TempCo: 25 ppm/C; Value_Code: 10k0; U/M: EA; Value: 10.0k; EIA_Code: E192; Tolerance_%: 0.1%; Res_ohm: 10k; SizeX_mm: 1.0; SizeY_mm: 0.5; SizeZ_mm: 0.6; Value2: .0625W; VDC_V: 50V; AEC Category: Q200
R52 = CMP-0026085-3: RES, 1.40 k, 1%, 0.063 W, AEC-Q200 Grade 0, 0402; Manufacturer: Vishay-Dale; Power_W: 63mW; TempCo: 100 ppm/C; Value_Code: 1k40; Value: 1.40k; EIA_Code: E96; Res_ohm: 1.4k; SizeX_mm: 1; SizeY_mm: 0.5; SizeZ_mm: 0.6; Value2: 0.063W; AEC Qualified: Y; VDC_V: 50V; AEC Category: Q200; AEC Grade: 0
R53 = CMP-0085900-1: RES, 1.00 M, 1%, 0.1 W, AEC-Q200 Grade 0, 0603; Manufacturer: Stackpole Electronics Inc; AEC Category: Q200; Res_ohm: 1M; SizeX_mm: 1.6; SizeY_mm: 0.8; Value: 1.00Meg; SizeAreaWB_mm2: 4.68; SizeArea_mm2: 1.28; Power_W: 100mW; AEC Qualified: Y; EIA_Code: E96; AEC Grade: 0; Value_Code: 1M00; Value2: 0.1W; TempCo: 100 ppm/C; SizeZ_mm: 1
R54 R57 = CMP-0026660-1: RES, 1.00 M, 1%, 0.1 W, 0402; Manufacturer: Panasonic; Power_W: 100mW; TempCo: 100 ppm/C; Value_Code: 1M00; U/M: EA; Value: 1.00Meg; EIA_Code: E96; Res_ohm: 1M; SizeX_mm: 1; SizeY_mm: 0.5; SizeZ_mm: 0.6; Value2: 0.1W; VDC_V: 50V; AEC Category: Q200
R56 R58 R59 R90-R93 = CMP-0081856-1: RES, 0, 0%, 0.2 W, AEC-Q200 Grade 0, 0402; Manufacturer: Vishay-Dale; SizeAreaWB_mm2: 3; SizeArea_mm2: 0.5; AEC Qualified: Y; AEC Category: Q200; Value: 0; SizeZ_mm: 0.6; Power_W: 200mW; VDC_V: 50V; Value2: 0.2W; SizeX_mm: 1
S1 = CMP-0002176-2: Switch, SPST 4 Pos, Top Actuated, SMT; Manufacturer: CTS Electrocomponents; CurrentRating_mA: 100A; PositionCount: 4; VDC_V: 50V; SwitchFunction: Off-On
S2 = CMP-0002170-2: Switch, Normally open, 2.3N force, 200k operations, SMD; Manufacturer: C&K Components; CurrentRating_mA: 1.001kA; SwitchFunction: Off-Mom; Circuit: SPST Switch; VDC_V: 32V; PositionCount: 1
TP1-TP7 = CMP-0003825-1: 1mm Test Point, SMT; Manufacturer: Any
U4 = CMP-0039269-4: 16-Bit Ultra-Low-Power Microcontroller, 128KB Flash, 8KB RAM, USB, 12Bit ADC, 2 USCIs, 32Bit HW MPY, RGC0064B (VQFN-64); Alternate Manufacturer: Texas Instruments; Alternate PartNumber: MSP430F5528IRGCR; Timers - 16-bit: 4; Rating: Catalog; SizeArea_mm2: 81.0; ADC: 12-bit SAR; Temp Sensor: Yes; GPIO: 47; ADC Channels: 16; SizeZ_mm: 1.0; Green_REACh: Passed; USCI_A (UART/LIN/IrDA/SPI): 2; AEC Qualified: N; AEC Category: Q200; CompType: IC; Flash(KB): 128; DMA: 3; USB: 1; Green_Lifecycle: Active; SRAM(B): 8192; SizeY_mm: 9.0; Multiplier: 32x32; SizeAreaWB_mm2: 121.0; Frequency(MHz): 25
U5 = CMP-0074267-1: Nanopower Supervisory Circuits for Automotive, DBV0005A (SOT-23-5); Alternate Manufacturer: Texas Instruments; SizeAreaWB_mm2: 14.82; U/M: EA; SizeZ_mm: 1.45; SizeX_mm: 2.8; SizeY_mm: 2.9; SizeArea_mm2: 8.12; CompType: IC
Y3 = CMP-0006148-5: Resonator, 4 MHz, 1000 ppm, 39 pF, SMD; Manufacturer: MuRata; TaMin_C: 0°C; Frequency Stability: 800 ppm; Frequency_Fixed: 4MHz; TaMax_C: 70°C; SizeAreaWB_mm2: 16.5; SizeArea_mm2: 9; SizeX_mm: 4.5; SizeY_mm: 2; SizeZ_mm: 1.2; AEC Category: Q200; AEC Qualified: N; Load Capacitance: 39 pF

## Sheet HSDC093D_867.SchDoc
size 431 x 279 mm; Date: Not shown in title block; ApprovedBy: Not shown in title block; CheckedBy: Not shown in title block; Author: Not shown in title block; CompanyName: Not shown in title block; Engineer: Not shown in title block; Organization: Not shown in title block; Address1: Not shown in title block; Address2: Not shown in title block; Address3: Not shown in title block; Address4: Not shown in title block; DocumentNumber: 3; Revision: Use project parameter SCH_Rev; SheetNumber: 3; SheetTotal: 5; PageSetup: Record=PageOptions¦CenterHorizontal=True¦CenterVertical=True¦PrintScale=1.00¦XCorrection=1.00¦YCorrection=1.00¦PrintKind=0¦BorderSize=5000000¦LeftOffset=0¦BottomOffset=0¦Orientation=2¦PaperLength=1000¦PaperWidth=1000¦Scale=100¦PaperSource=15¦PrintQuality=600¦MediaType=1¦DitherType=10¦PaperKind=Letter¦PrintScaleMode=1
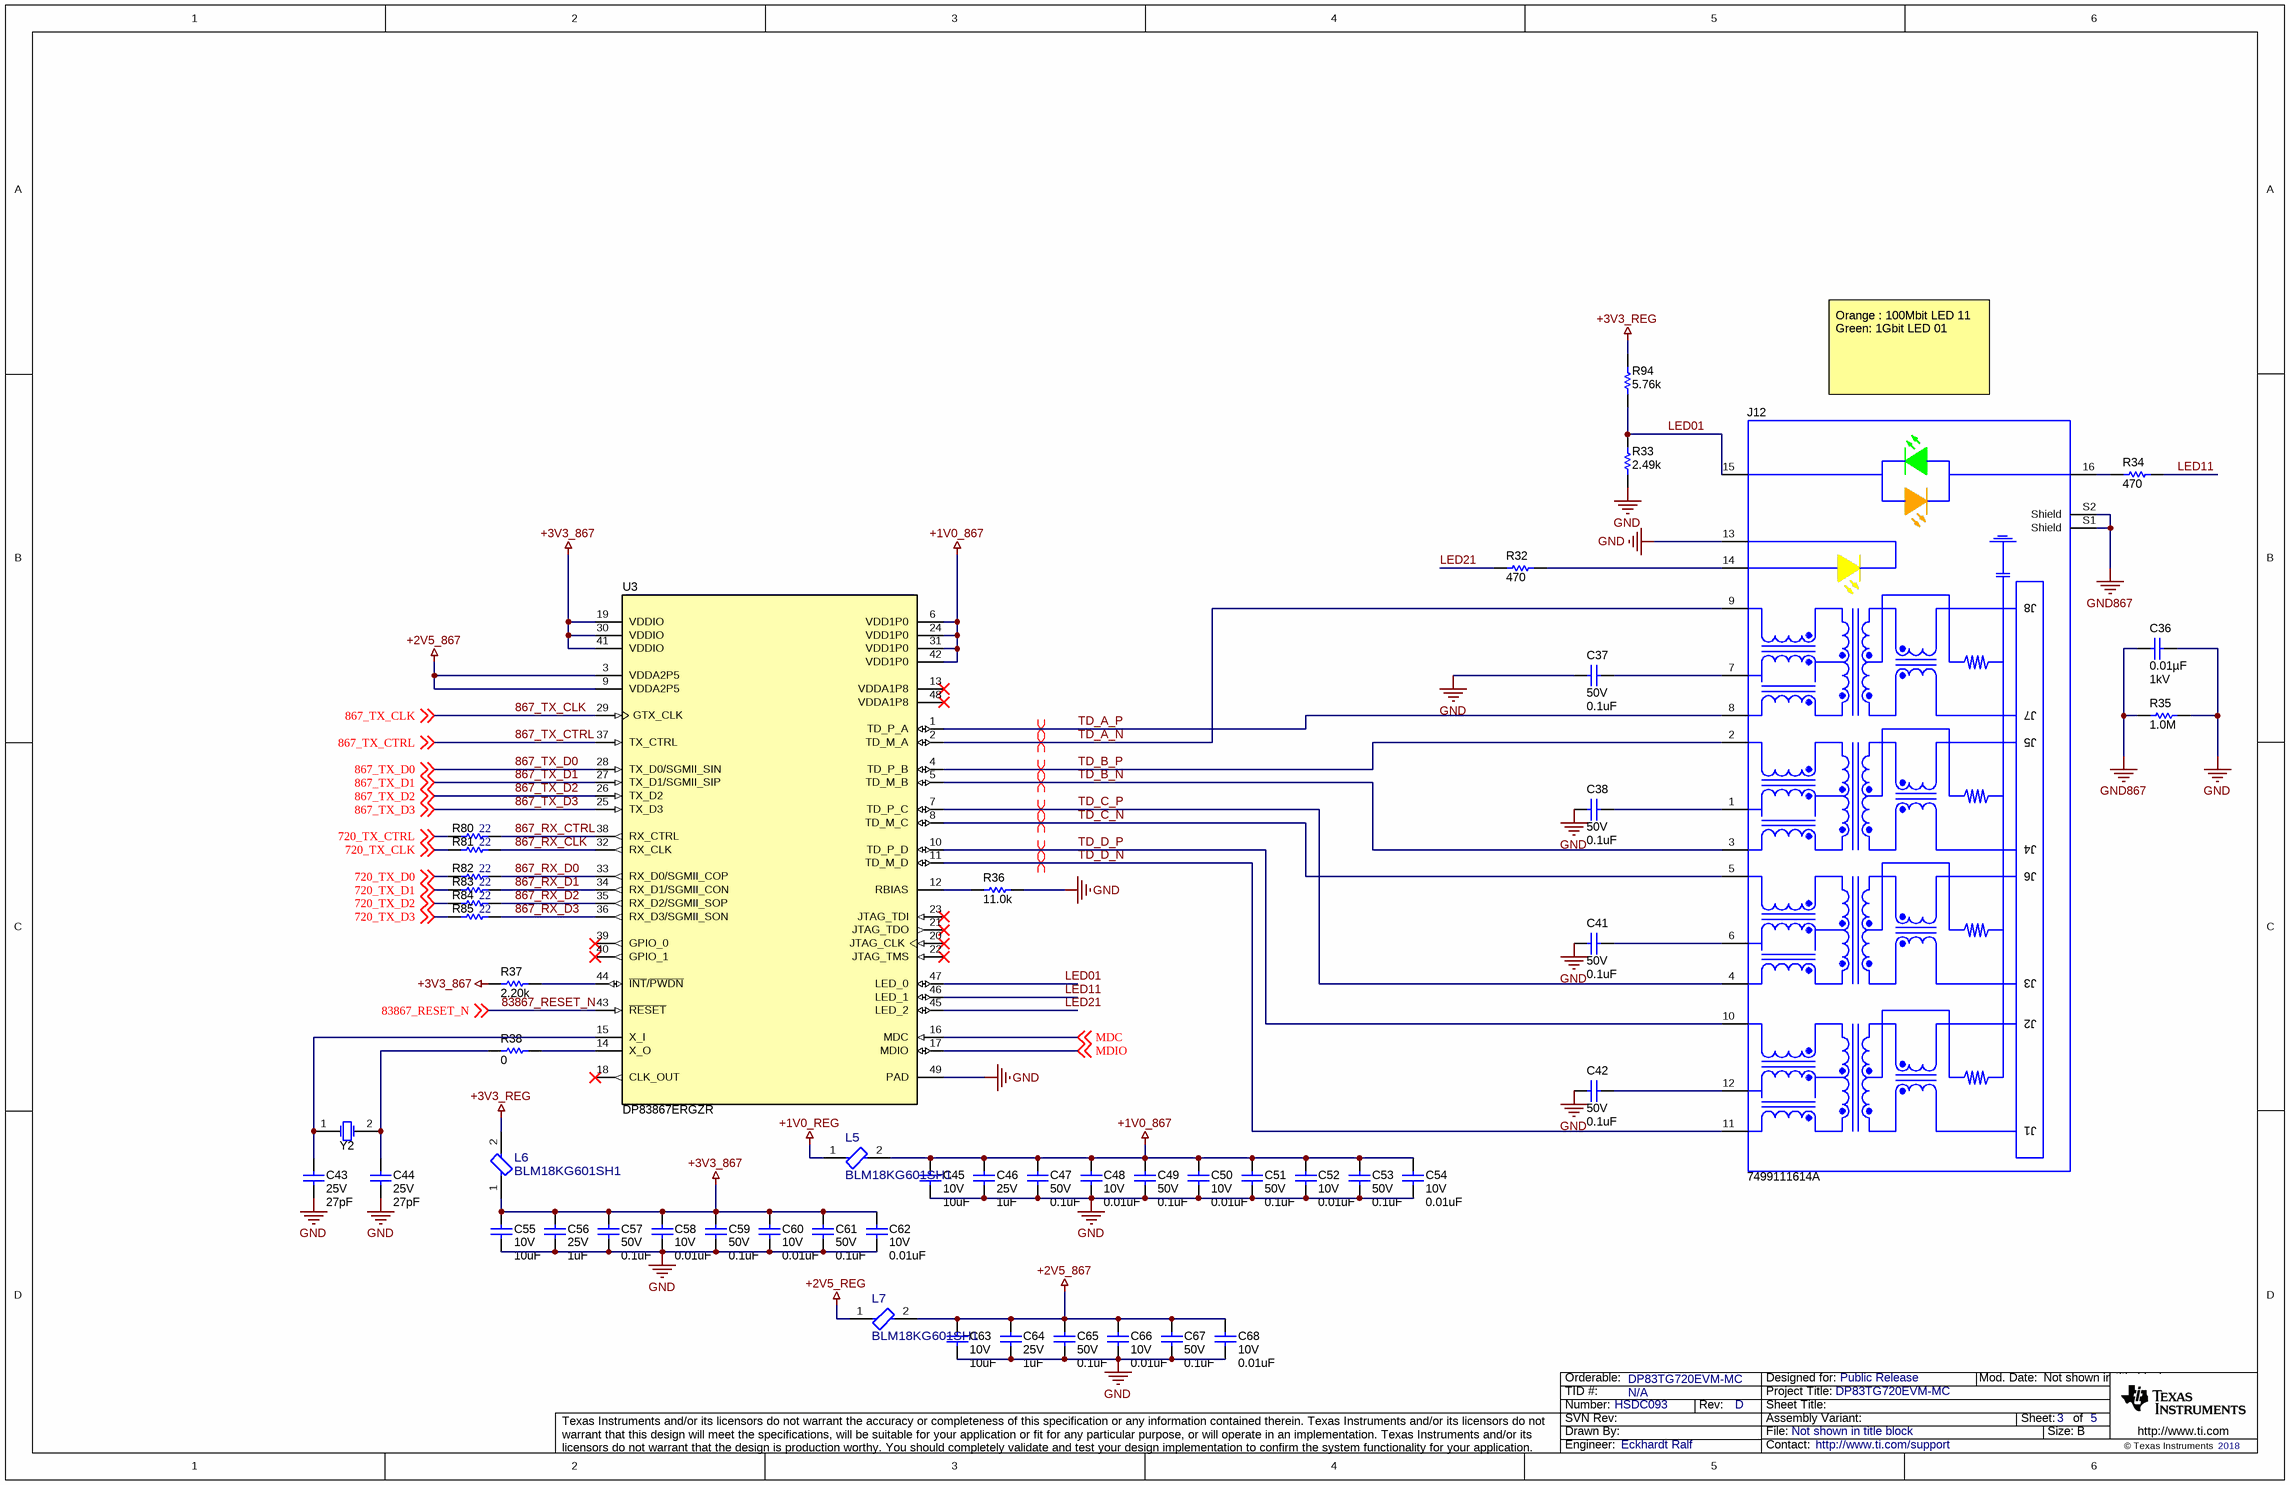
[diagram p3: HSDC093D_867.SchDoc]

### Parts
C36  ValueDisplayed: 0.01µF  VDC_V: 1kV  [1206]  (hidden comment: C1206X103KDRAC7800)
C37  VDC_V: 50V  ValueDisplayed: 0.1uF  [0402]  (hidden comment: C1005X5R1H104K050BB)
C38  VDC_V: 50V  ValueDisplayed: 0.1uF  [0402]  (hidden comment: C1005X5R1H104K050BB)
C41  VDC_V: 50V  ValueDisplayed: 0.1uF  [0402]  (hidden comment: C1005X5R1H104K050BB)
C42  VDC_V: 50V  ValueDisplayed: 0.1uF  [0402]  (hidden comment: C1005X5R1H104K050BB)
C43  VDC_V: 25V  ValueDisplayed: 27pF  [0402S]  (hidden comment: GRM1555C1E270JA01D)
C44  VDC_V: 25V  ValueDisplayed: 27pF  [0402S]  (hidden comment: GRM1555C1E270JA01D)
C45  VDC_V: 10V  ValueDisplayed: 10uF  [0402]  (hidden comment: GRM155R61A106ME11)
C46  VDC_V: 25V  ValueDisplayed: 1uF  [0402]  (hidden comment: GRM155R61E105KA12D)
C47  VDC_V: 50V  ValueDisplayed: 0.1uF  [0402]  (hidden comment: C1005X5R1H104K050BB)
C48  VDC_V: 10V  ValueDisplayed: 0.01uF  [0402]  (hidden comment: GRM155R61A103KA01D)
C49  VDC_V: 50V  ValueDisplayed: 0.1uF  [0402]  (hidden comment: C1005X5R1H104K050BB)
C50  VDC_V: 10V  ValueDisplayed: 0.01uF  [0402]  (hidden comment: GRM155R61A103KA01D)
C51  VDC_V: 50V  ValueDisplayed: 0.1uF  [0402]  (hidden comment: C1005X5R1H104K050BB)
C52  VDC_V: 10V  ValueDisplayed: 0.01uF  [0402]  (hidden comment: GRM155R61A103KA01D)
C53  VDC_V: 50V  ValueDisplayed: 0.1uF  [0402]  (hidden comment: C1005X5R1H104K050BB)
C54  VDC_V: 10V  ValueDisplayed: 0.01uF  [0402]  (hidden comment: GRM155R61A103KA01D)
C55  VDC_V: 10V  ValueDisplayed: 10uF  [0402]  (hidden comment: GRM155R61A106ME11)
C56  VDC_V: 25V  ValueDisplayed: 1uF  [0402]  (hidden comment: GRM155R61E105KA12D)
C57  VDC_V: 50V  ValueDisplayed: 0.1uF  [0402]  (hidden comment: C1005X5R1H104K050BB)
C58  VDC_V: 10V  ValueDisplayed: 0.01uF  [0402]  (hidden comment: GRM155R61A103KA01D)
C59  VDC_V: 50V  ValueDisplayed: 0.1uF  [0402]  (hidden comment: C1005X5R1H104K050BB)
C60  VDC_V: 10V  ValueDisplayed: 0.01uF  [0402]  (hidden comment: GRM155R61A103KA01D)
C61  VDC_V: 50V  ValueDisplayed: 0.1uF  [0402]  (hidden comment: C1005X5R1H104K050BB)
C62  VDC_V: 10V  ValueDisplayed: 0.01uF  [0402]  (hidden comment: GRM155R61A103KA01D)
C63  VDC_V: 10V  ValueDisplayed: 10uF  [0402]  (hidden comment: GRM155R61A106ME11)
C64  VDC_V: 25V  ValueDisplayed: 1uF  [0402]  (hidden comment: GRM155R61E105KA12D)
C65  VDC_V: 50V  ValueDisplayed: 0.1uF  [0402]  (hidden comment: C1005X5R1H104K050BB)
C66  VDC_V: 10V  ValueDisplayed: 0.01uF  [0402]  (hidden comment: GRM155R61A103KA01D)
C67  VDC_V: 50V  ValueDisplayed: 0.1uF  [0402]  (hidden comment: C1005X5R1H104K050BB)
C68  VDC_V: 10V  ValueDisplayed: 0.01uF  [0402]  (hidden comment: GRM155R61A103KA01D)
J12  7499111614A  [Wurth_7499111614A]
L5  BLM18KG601SH1  [FP-BLM18KG601SH1_0603 (1608 Metric)-MFG]
L6  BLM18KG601SH1  [FP-BLM18KG601SH1_0603 (1608 Metric)-MFG]
L7  BLM18KG601SH1  [FP-BLM18KG601SH1_0603 (1608 Metric)-MFG]
R32  ValueDisplayed: 470  [0402]  (hidden comment: RC0402FR-07470RL)
R33  ValueDisplayed: 2.49k  [0402]  (hidden comment: CRCW04022K49FKED)
R34  ValueDisplayed: 470  [0402]  (hidden comment: RC0402FR-07470RL)
R35  ValueDisplayed: 1.0M  [1206]  (hidden comment: CRCW12061M00JNEA)
R36  ValueDisplayed: 11.0k  [0402]  (hidden comment: CRCW040211K0FKED)
R37  ValueDisplayed: 2.20k  [0402]  (hidden comment: ERJ-2RKF2201X)
R38  ValueDisplayed: 0  [0402]  (hidden comment: CRCW04020000Z0EDHP)
R80  ValueDisplayed: 22  [0402]  (hidden comment: CRCW040222R0JNED)
R81  ValueDisplayed: 22  [0402]  (hidden comment: CRCW040222R0JNED)
R82  ValueDisplayed: 22  [0402]  (hidden comment: CRCW040222R0JNED)
R83  ValueDisplayed: 22  [0402]  (hidden comment: CRCW040222R0JNED)
R84  ValueDisplayed: 22  [0402]  (hidden comment: CRCW040222R0JNED)
R85  ValueDisplayed: 22  [0402]  (hidden comment: CRCW040222R0JNED)
R94  ValueDisplayed: 5.76k  [0402]  (hidden comment: CRCW04025K76FKED)
U3  DP83867ERGZR  [RGZ0048B]
Y2  NX5032GA-25.000M-STD-CSK-4  [NDK_NX5032GA]  (value not drawn)

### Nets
+1V0_867: C45.1 C46.1 C47.1 C48.1 C49.1 C50.1 C51.1 C52.1 C53.1 C54.1 L5.2 U3.6(VDD1P0) U3.24(VDD1P0) U3.31(VDD1P0) U3.42(VDD1P0)
+1V0_REG: L5.1
+2V5_867: C63.1 C64.1 C65.1 C66.1 C67.1 C68.1 L7.2 U3.3(VDDA2P5) U3.9(VDDA2P5)
+2V5_REG: L7.1
+3V3_867: C55.1 C56.1 C57.1 C58.1 C59.1 C60.1 C61.1 C62.1 L6.1 R37.1 U3.19(VDDIO) U3.30(VDDIO) U3.41(VDDIO)
+3V3_REG: L6.2 R94.2
GND: C36.1 C37.1 C38.1 C41.1 C42.1 C43.2 C44.1 C45.2 C46.2 C47.2 C48.2 C49.2 C50.2 C51.2 C52.2 C53.2 C54.2 C55.2 C56.2 C57.2 C58.2 C59.2 C60.2 C61.2 C62.2 C63.2 C64.2 C65.2 C66.2 C67.2 C68.2 J12.13(K) R33.1 R35.2 R36.2 U3.49(PAD)
GND867: C36.2 J12.S1(Shield) J12.S2(Shield) R35.1
720_TX_CLK: R81.1 ; off-sheet 720_TX_CLK
720_TX_CTRL: R80.1 ; off-sheet 720_TX_CTRL
720_TX_D0: R82.1 ; off-sheet 720_TX_D0
720_TX_D1: R83.1 ; off-sheet 720_TX_D1
720_TX_D2: R84.1 ; off-sheet 720_TX_D2
720_TX_D3: R85.1 ; off-sheet 720_TX_D3
867_RX_CLK: R81.2 U3.32(RX_CLK)
867_RX_CTRL: R80.2 U3.38(RX_CTRL)
867_RX_D0: R82.2 U3.33(RX_D0/SGMII_COP)
867_RX_D1: R83.2 U3.34(RX_D1/SGMII_CON)
867_RX_D2: R84.2 U3.35(RX_D2/SGMII_SOP)
867_RX_D3: R85.2 U3.36(RX_D3/SGMII_SON)
867_TX_CLK: U3.29(GTX_CLK) ; off-sheet 867_TX_CLK
867_TX_CTRL: U3.37(TX_CTRL) ; off-sheet 867_TX_CTRL
867_TX_D0: U3.28(TX_D0/SGMII_SIN) ; off-sheet 867_TX_D0
867_TX_D1: U3.27(TX_D1/SGMII_SIP) ; off-sheet 867_TX_D1
867_TX_D2: U3.26(TX_D2) ; off-sheet 867_TX_D2
867_TX_D3: U3.25(TX_D3) ; off-sheet 867_TX_D3
83867_RESET_N: U3.43(~{RESET}) ; off-sheet 83867_RESET_N
LED01: J12.15 R33.2 R94.1 U3.47(LED_0)
LED11: R34.1 U3.46(LED_1)
LED21: R32.2 U3.45(LED_2)
MDC: U3.16(MDC) ; off-sheet MDC
MDIO: U3.17(MDIO) ; off-sheet MDIO
TD_A_N: J12.9 U3.2(TD_M_A)
TD_A_P: J12.8 U3.1(TD_P_A)
TD_B_N: J12.3 U3.5(TD_M_B)
TD_B_P: J12.2 U3.4(TD_P_B)
TD_C_N: J12.5 U3.8(TD_M_C)
TD_C_P: J12.4 U3.7(TD_P_C)
TD_D_N: J12.11 U3.11(TD_M_D)
TD_D_P: J12.10 U3.10(TD_P_D)
NetC37_2: C37.2 J12.7
NetC38_2: C38.2 J12.1
NetC41_2: C41.2 J12.6
NetC42_2: C42.2 J12.12
NetC43_1: C43.1 U3.15(X_I) Y2.1(OSC1)
NetC44_2: C44.2 R38.2 Y2.2(OSC2)
NetJ12_14: J12.14(A) R32.1
NetJ12_16: J12.16 R34.2
NetR36_1: R36.1 U3.12(RBIAS)
NetR37_2: R37.2 U3.44(~{INT}/~{PWDN})
NetR38_1: R38.1 U3.14(X_O)

Not connected (* = marked no-connect by the designer): U3 13(VDDA1P8)* 18(CLK_OUT)* 20(JTAG_CLK)* 21(JTAG_TDO)* 22(JTAG_TMS)* 23(JTAG_TDI)* 39(GPIO_0)* 40(GPIO_1)* 48(VDDA1P8)*

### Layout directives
differential pair: TD_A_N, TD_A_P, TD_B_N, TD_B_P, TD_C_N, TD_C_P, TD_D_N, TD_D_P

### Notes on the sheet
- Orange : 100Mbit LED 11
  Green: 1Gbit LED 01

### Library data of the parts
C36 = CMP-0085177-1: as C70 on sheet HSDC093D_Controller
C37 C38 C41 C42 C47 C49 C51 C53 C57 C59 C61 C65 C67 = CMP-0006279-2: as C82 on sheet HSDC093D_Power_Sup
C43 C44 = CMP-0077091-1: CAP, CERM, 27 pF, 25 V,+/- 5%, C0G/NP0, 0402; Manufacturer: MuRata; SizeAreaWB_mm2: 3.0; SizeArea_mm2: 0.5; AEC Qualified: N; AEC Category: Q200; Value: 27pF; TaMax_C: 125°C; SizeZ_mm: 0.6; TaMin_C: -55°C; U/M: EA; SizeX_mm: 1.0; Cap_Case: 0402
C45 C55 C63 = CMP-0006564-2: as C85 on sheet HSDC093D_Power_Sup
C46 C56 C64 = CMP-0006608-2: as C86 on sheet HSDC093D_Power_Sup
C48 C50 C52 C54 C58 C60 C62 C66 C68 = CMP-0006561-2: CAP, CERM, 0.01 uF, 10 V, +/- 10%, X5R, 0402; Manufacturer: MuRata; TaMin_C: -55°C; Polarized: N; SizeAreaWB_mm2: 3; Value1: Unknown; U/M: EA; Value: 0.01uF; TaMax_C: 85°C; SizeZ_mm: 0.6; SizeX_mm: 1; SizeY_mm: 0.5; Cap_F: 10nF; AEC Category: Q200
J12 = CMP-0085931-1: Connector, 1 Port RJ45, Gold, R/A, TH; Manufacturer: Wurth Elektronik; Gender: Female
L5-L7 = CMP-0089848-1: 600 Ohms @ 100MHz 1 Power Line Ferrite Bead 0603 (1608 Metric) 1.3A 150mOhm; Manufacturer: Murata; Tolerance_%: 25%; SizeZ_mm: 0.95mm; Impedance At Frequency: 600Ω @ 100MHz; AEC Qualified: Yes; AEC Grade: Grade 1; DCR_ohm: 0.15
R32 R34 = CMP-0026736-1: as R72 on sheet HSDC093D_Power_Sup
R33 = CMP-0026237-2: RES, 2.49 k, 1%, 0.063 W, AEC-Q200 Grade 0, 0402; Manufacturer: Vishay-Dale; Power_W: 63mW; TempCo: 100 ppm/C; Value_Code: 2k49; Value: 2.49k; EIA_Code: E96; SizeX_mm: 1; SizeY_mm: 0.5; SizeZ_mm: 0.6; Value2: 0.063W; AEC Qualified: Y; VDC_V: 50V; AEC Category: Q200; AEC Grade: 0
R35 = CMP-0018610-3: RES, 1.0 M, 5%, 0.25 W, AEC-Q200 Grade 0, 1206; Manufacturer: Vishay-Dale; Power_W: 250mW; TempCo: 200 ppm/C; Value_Code: 1M00; Value: 1.0Meg; EIA_Code: E24; Res_ohm: 1M; SizeX_mm: 3.2; SizeY_mm: 1.6; SizeZ_mm: 1.35; Value2: 0.25W; SizeArea_mm2: 5.12; AEC Qualified: Y; VDC_V: 200V; AEC Category: Q200; AEC Grade: 0
R36 = CMP-0025975-3: RES, 11.0 k, 1%, 0.063 W, AEC-Q200 Grade 0, 0402; Manufacturer: Vishay-Dale; Power_W: 63mW; TempCo: 100 ppm/C; Value_Code: 11k0; Value: 11.0k; EIA_Code: E96; Res_ohm: 11k; SizeX_mm: 1; SizeY_mm: 0.5; SizeZ_mm: 0.6; Value2: 0.063W; AEC Qualified: Y; VDC_V: 50V; AEC Category: Q200; AEC Grade: 0
R37 = CMP-0026681-1: as R45 on sheet HSDC093D_Controller
R38 = CMP-0081856-1: as R56 on sheet HSDC093D_Controller
R80-R85 = CMP-0026880-3: RES, 22, 5%, 0.063 W, AEC-Q200 Grade 0, 0402; Manufacturer: Vishay-Dale; Power_W: 63mW; TempCo: 200 ppm/C; Value_Code: 22R0; Value: 22; EIA_Code: E24; SizeX_mm: 1; SizeY_mm: 0.5; SizeZ_mm: 0.6; Value2: 0.063W; AEC Qualified: Y; VDC_V: 50V; AEC Category: Q200; AEC Grade: 0
R94 = CMP-0026468-2: RES, 5.76 k, 1%, 0.063 W, AEC-Q200 Grade 0, 0402; Manufacturer: Vishay-Dale; Power_W: 63mW; TempCo: 100 ppm/C; Value_Code: 5k76; Value: 5.76k; EIA_Code: E96; SizeX_mm: 1; SizeY_mm: 0.5; SizeZ_mm: 0.6; Value2: 0.063W; AEC Qualified: Y; VDC_V: 50V; AEC Category: Q200; AEC Grade: 0
U3 = CMP-0076013-2: Extended Temperature Gigabit Ethernet PHY with SGMII, RGZ0048B (VQFN-48); Manufacturer: Texas Instruments; Alternate PartNumber: DP83867ERGZT; SizeX_mm: 7; CompType: IC; SizeZ_mm: 1; SizeArea_mm2: 49; SizeAreaWB_mm2: 81; U/M: EA
Y2 = CMP-0004665-3: Crystal, 25 MHz,  SMD; Manufacturer: NDK; TaMax_C: 150°C; TaMin_C: -40°C; Frequency Stability: +/-30ppm; Frequency_Fixed: 25MHz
